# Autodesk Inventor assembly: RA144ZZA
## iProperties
Category: PARTsolutions
Created: 2011-07
Part Number: RA144ZZA
Catalog Web Link: www.cadenas.de
Description: With double shield ZZ -
Document SubType Name: Assembly
Designer: PARTsolutions
NB: RA144ZZA
NN: With double shield ZZ
NBSYN: RA144ZZA
LINA: RA144ZZA
PSOL_MULTISOLIDPART: 0.0
SD: 3.175
D: 6.350
B: 2.380
B1: 2.779
D1: 7.52
D2: 7.52
C1: 0.58
C2: 0.79
R: 0.08
ORDER: RA144ZZA
CR: 284
COR: 96
CRF: 29
CORF: 10
LSG: 59000
LSO: 70000
MASS: 0.27
ORDER1: R144
WSS: RA144ZA
WDS: RA144ZZA
UTWF: FLR144
FORSS: FLRA144ZA
FORDS: FLRA144ZZA
DA1: 3.9
DA2: 4
DA: 5.5
RAS: 0.08
MASS1: 0.33
VERS: 3
X: 1.587
N: 9
O: 14.954
RB: 0.470
PPATH: iss_asmtpl.prj
KT: DUMMY
CreationOption_UseAsmMates: 0
SUPPLIER: NTN
ARTICLENO: RA144ZZA
BOMINFO: RA144ZZA
CREATOR: CADENAS GmbH
PSOL_IDENT_0: {\\10.0.0.251\ps_data\23d-libs\ntn\ball_roller_bearings\miniature_extra_small_bb\inch_system_sizes\i
PSOL_IDENT_1: ss_zz_asmtab.prj},181 {VTYP=3D},{STYP=ASSTAB},{NB=RA144ZZA},{LINA=RA144ZZA},{NN=With double shield Z
PSOL_IDENT_2: Z},{DATE=11.12.2007 08:48:22},{GEOMDATE=02.04.2007},{VERSION=},{LINEID=16080},{LINESUBID=-1},{WBVAR=
PSOL_IDENT_3: }  {NB=RA144ZZA},{LINA=RA144ZZA},{KT=DUMMY},{IDNR=},{SD=3.175},{D=6.350},{B=2.380},{B1=2.779},{D1=7.
PSOL_IDENT_4: 52},{D2=7.52},{C1=0.58},{C2=0.79},{R=0.08},{ORDER=RA144ZZA},{CR=284},{COR=96},{CRF=29},{CORF=10},{LS
PSOL_IDENT_5: G=59000},{LSO=70000},{MASS=0.27},{ORDER1=R144},{WSS=RA144ZA},{WDS=RA144ZZA},{UTWF=FLR144},{FORSS=FLR
PSOL_IDENT_6: A144ZA},{FORDS=FLRA144ZZA},{DA1=3.9},{DA2=4},{DA=5.5},{RAS=0.08},{MASS1=0.33},{VERS=3},{X=1.5875},{N
PSOL_IDENT_7: =9},{O=14.95425},{RB=0.4699},{PPATH=iss_asmtpl.prj}
Title: RA144ZZA
Author: Cadenas PARTsolutions
